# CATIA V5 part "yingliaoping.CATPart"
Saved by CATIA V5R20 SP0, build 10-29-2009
Part number: Part1
Material "Multicoloured Flag"
Material "Wallpaper 3": density 500 kg/m3
Bounding box of the stored display mesh (mm): x -25 to 25, y -25 to 25.2, z 0 to 110
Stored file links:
  E:\180212416 李乐\ping.CATPart
  D:\CATIA20\win_b64\startup\materials\Catalog.CATMaterial
  D:\CATIA20\win_b64\startup\materials\bark.jpg
  D:\CATIA20\win_b64\startup\materials\canvas.jpg
  D:\CATIA20\win_b64\startup\materials\wallpaper_03.jpg
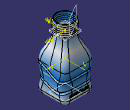
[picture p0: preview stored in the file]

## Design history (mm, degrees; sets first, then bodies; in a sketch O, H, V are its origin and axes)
Set1
  Sketch1 on xy-plane, origin (0, 0, 0), H (1, 0, 0), V (0, 1, 0)
    line L1 (25, 25) -> (25, -25)
    line L2 (25, -25) -> (-25, -25)
    line L3 (-25, -25) -> (-25, 25)
    line L4 (-25, 25) -> (25, 25)
    distance L2 L4 = 50
    distance L1 L3 = 50
    vertical: L1 V, L3 V
    horizontal: L2 H, L4 H
    equidistance: L1 L3 O, L2 L4 O
  Sketch2 on face of Pad1 from Sketch1.L1, origin (25, 0, 0), H (0, 1, 0), V (0, 0, 1)
    spline S1 through (-45.7445, 16.4161) (-7.2571, 21.8478) (6.5741, 17.0844) (41.6698, 25.8205) (42.718, 25.8205)
  Extrude1: Element1 Sketch2, Lim1 55, Lim2 55
  MultiSel1: CommonCtxFeats ({extract ExtractElem face of Fillet1}; {extract ExtractElem face of Pad1 from Sketch1.L4}; {extract ExtractElem face of Fillet1}; {extract ExtractElem face of Pad1 from Sketch1.L3}; {extract ExtractElem face of Fillet1}; {extract ExtractElem face of Pad1 from Sketch1.L2}; {extract ExtractElem face of Fillet1}; {extract ExtractElem face of Pad1 from Sketch1.L1})
  Sketch3 on face of Pad1 from Sketch1.L1, origin (25, 0, 0), H (0, 1, 0), V (0, 0, 1)
    spline S1 through (-46.1477, 34.2452) (-9.0174, 41.4031) (4.5623, 34.1326) (38.6801, 46.6967)
  Extrude2: Element1 Sketch3, Lim1 55, Lim2 55
  MultiSel2: CommonCtxFeats ({extract ExtractElem face of Pad1 from Sketch1.L4}; {extract ExtractElem face of Fillet1}; {extract ExtractElem face of Pad1 from Sketch1.L3}; {extract ExtractElem face of Fillet1}; {extract ExtractElem face of Pad1 from Sketch1.L2}; {extract ExtractElem face of Fillet1}; {extract ExtractElem face of Pad1 from Sketch1.L1}; {extract ExtractElem face of Fillet1})
  Join1: Elements ({intersect ToIntersect1 {extract ExtractElem face of Fillet1}, ToIntersect2 Extrude1}; {intersect ToIntersect1 {extract ExtractElem face of Pad1 from Sketch1.L4}, ToIntersect2 Extrude1}; {intersect ToIntersect1 {extract ExtractElem face of Fillet1}, ToIntersect2 Extrude1}; {intersect ToIntersect1 {extract ExtractElem face of Pad1 from Sketch1.L3}, ToIntersect2 Extrude1}; {intersect ToIntersect1 {extract ExtractElem face of Fillet1}, ToIntersect2 Extrude1}; {intersect ToIntersect1 {extract ExtractElem face of Pad1 from Sketch1.L2}, ToIntersect2 Extrude1}; {intersect ToIntersect1 {extract ExtractElem face of Fillet1}, ToIntersect2 Extrude1}; {intersect ToIntersect1 {extract ExtractElem face of Pad1 from Sketch1.L1}, ToIntersect2 Extrude1})
  Join2: Elements ({intersect ToIntersect1 {extract ExtractElem face of Pad1 from Sketch1.L4}, ToIntersect2 Extrude2}; {intersect ToIntersect1 {extract ExtractElem face of Fillet1}, ToIntersect2 Extrude2}; {intersect ToIntersect1 {extract ExtractElem face of Pad1 from Sketch1.L3}, ToIntersect2 Extrude2}; {intersect ToIntersect1 {extract ExtractElem face of Fillet1}, ToIntersect2 Extrude2}; {intersect ToIntersect1 {extract ExtractElem face of Pad1 from Sketch1.L2}, ToIntersect2 Extrude2}; {intersect ToIntersect1 {extract ExtractElem face of Fillet1}, ToIntersect2 Extrude2}; {intersect ToIntersect1 {extract ExtractElem face of Pad1 from Sketch1.L1}, ToIntersect2 Extrude2}; {intersect ToIntersect1 {extract ExtractElem face of Fillet1}, ToIntersect2 Extrude2})
  Plane1: type Normal, Curve Join1, RefPoint vertex [face of MultiSel1 | face of MultiSel1]
  Sketch4 on Plane1, origin (-12, 0, 0), H (0, -1, 0), V (0, 0, 1)
    circle A1 centre (25.0924, 26.5673) radius 2
Body1 (main body), material "Multicoloured Flag"
  Pad1: profile Sketch1, direction (0, 0, 1), length 50
  Fillet1: on edge [face of Pad1 from Sketch1.L3 | face of Pad1 from Sketch1.L4]; edge [face of Pad1 from Sketch1.L4 | face of Pad1 from Sketch1.L1]; edge [face of Pad1 from Sketch1.L1 | face of Pad1 from Sketch1.L2]; edge [face of Pad1 from Sketch1.L2 | face of Pad1 from Sketch1.L3]
  Fillet2: radius 8, on start face of Pad1
  Plane2: type Offset, RefPlane end face of Pad1, Offset 40, reversed
  Sketch5 on Plane2, origin (0, 0, 90), H (1, 0, 0), V (0, -1, 0)
    circle A1 centre (0, 0) radius 15
    radius A1 = 15
  Pad2: profile Sketch5, direction (0, 0, 1), length 20
  Sketch6 on end face of Pad1, origin (0, 0, 50), H (1, 0, 0), V (0, 1, 0)
    point P1 (25, 0)
    coincidence: P1 H
  Sketch7 on start face of Pad2, origin (0, 0, 90), H (1, 0, 0), V (0, -1, 0)
    point P1 (15, 0)
    distance P1 V = 15
    coincidence: P1 H
  Loft1: solid, Sections ({boundary Boundary {extract ExtractElem end face of Pad1}}; {boundary Boundary {extract ExtractElem start face of Pad2}}), StartFace end face of Pad1, EndFace start face of Pad2
  Slot1: profile Sketch4, centre curve Join1
  Plane3: type Normal, Curve Join2, RefPoint vertex [face of MultiSel2 | face of MultiSel2]
  Sketch8 on Plane3, origin (0, 9.9333, -1.5997), H (1, 0, 0), V (0, 0.0894, 0.996)
    circle A1 centre (25.0134, 35.7726) radius 2
  Slot2: profile Sketch8, centre curve Join2
  Shell1: IntOffset 1, Face end face of Pad2, ExtOffset 0
  Plane4: type Offset, RefPlane Plane2, Offset 2, reversed
  Sketch9 on Plane4, origin (0, 0, 92), H (1, 0, 0), V (0, -1, 0)
    point P1 (15, 0)
    distance P1 V = 15
    coincidence: P1 H
  Helix1: Direction Z axis, RefPoint Sketch9, Pitch 3, Height 16, TaperAngle 0
  Point1: type OnCurve, Support Helix1, Length 5
  Line1: type Normal, RefPoint Sketch9, RefSkin face of Loft1, Start 0, End 5
  Connect1: Curve1 Helix1, Point1 Point1, Tension1 1, Curve2 Line1, Point2 vertex of Line1, Tension2 1
  Body2
    Sketch10 on Plane2, origin (0, 0, 90), H (1, 0, 0), V (0, -1, 0)
      circle A1 centre (0, 0) radius 14
      radius A1 = 14
    Pad3: profile Sketch10, direction (0, 0, 1), length 20
  Remove1: tool Body2
  Body3
    Sketch11 on Plane2, origin (0, 0, 90), H (1, 0, 0), V (0, -1, 0)
      circle A1 centre (0, 0) radius 14
      radius A1 = 14
    Pad4: profile Sketch11, direction (0, 0, -1), length 30, mirrored extent
  Remove2: tool Body3
  Body4
    Sketch12 on Plane2, origin (0, 0, 90), H (1, 0, 0), V (0, -1, 0)
      circle A1 centre (0, 0) radius 14
      radius A1 = 14
    Pad5: profile Sketch12, direction (0, 0, 1), length 30
  Remove3: tool Body4
Body5, material "Wallpaper 3"
  Point2: type OnCurve, Support Connect1, RefPoint vertex of Helix1, Length 5
  Line2: type Normal, RefPoint vertex of Helix1, RefSkin face of Pad2 from Sketch5.A1, Start 0, End 5
  Connect2: Curve1 Connect1, Point1 Point2, Tension1 1, Curve2 Line2, Point2 vertex of Line2, Tension2 1
  Sketch13 on face of Pad1 from Sketch1.L4, origin (0, 25, 0), H (-1, 0, 0), V (0, 0, 1)
    polyline C1
    polyline C2
    polyline C3
    polyline C4
    polyline C5
    polyline C6
    polyline C7
    polyline C8
    polyline C9
    polyline C10
    polyline C11
    polyline C12
    polyline C13
  Pad6: profile Sketch13, direction (0, 1, 0), length 0.2
  Plane5: type Normal, Curve Connect2, RefPoint vertex of Connect2
  Circle1: type CtrRad, Start 0, End 180, Center vertex of Connect2, Support Plane5, Radius 1, FirstDirection (0.866, 0.5, 0)
  Rib1: profile Circle1, centre curve Connect2
  Body6
    Sketch14 on end face of Pad2, origin (0, 0, 110), H (1, 0, 0), V (0, 1, 0)
      circle A1 centre (0, 0) radius 14
      radius A1 = 14
    Pad7: profile Sketch14, direction (0, 0, 1), length 30, mirrored extent
  Remove4: tool Body6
